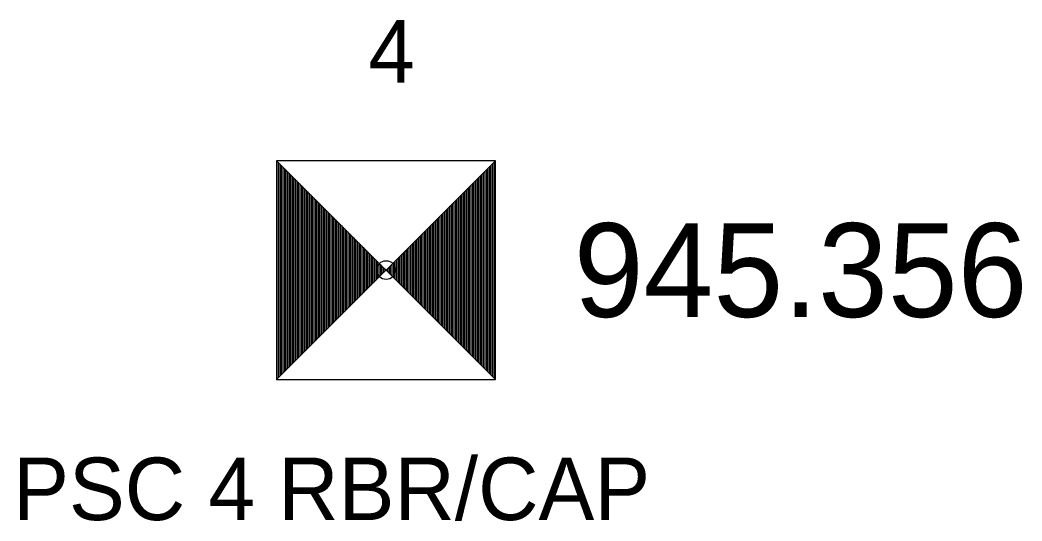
# Model space of a CAD drawing. Extents: x 1448136 to 1453623, y 1125056 to 1128842.
# Drawn here: x 1448135.69 to 1448151.7, y 1126641.44 to 1126649.46 of the extents above; entities that cross this region are included whole.
import ezdxf

# ---------------------------------------------------------------- set-up
doc = ezdxf.new("R2010")
doc.units = 0
for name, color, linetype in [('RD_HC_Survey', 7, 'Continuous'), ('RD_HC_Survey_ELEV', 7, 'Continuous'), ('RD_HC_txCode', 7, 'Continuous'), ('RD_SMD_Locator', 7, 'Continuous')]:
    doc.layers.add(name, color=color, linetype=linetype)

msp = doc.modelspace()

# ---------------------------------------------------------------- linework, layer by layer
at = {"layer": 'RD_HC_Survey'}
for p, q in [((1448139.787, 1126647.205), (1448143.287, 1126643.705)), ((1448143.287, 1126647.205), (1448139.787, 1126643.705)), ((1448139.812, 1126647.18), (1448139.812, 1126643.73)), ((1448143.262, 1126647.18), (1448143.262, 1126643.73)), ((1448139.837, 1126647.156), (1448139.837, 1126643.755)), ((1448139.861, 1126647.131), (1448139.861, 1126643.779)), ((1448139.886, 1126647.106), (1448139.886, 1126643.804)), ((1448139.911, 1126647.081), (1448139.911, 1126643.829)), ((1448139.936, 1126647.057), (1448139.936, 1126643.854)), ((1448139.96, 1126647.032), (1448139.96, 1126643.878)), ((1448139.985, 1126647.007), (1448139.985, 1126643.903)), ((1448143.089, 1126647.007), (1448143.089, 1126643.903)), ((1448143.114, 1126647.032), (1448143.114, 1126643.878)), ((1448143.139, 1126647.057), (1448143.139, 1126643.854)), ((1448143.163, 1126647.081), (1448143.163, 1126643.829)), ((1448143.188, 1126647.106), (1448143.188, 1126643.804)), ((1448143.213, 1126647.131), (1448143.213, 1126643.779)), ((1448143.238, 1126647.156), (1448143.238, 1126643.755)), ((1448140.01, 1126646.982), (1448140.01, 1126643.928)), ((1448140.035, 1126646.958), (1448140.035, 1126643.953)), ((1448140.059, 1126646.933), (1448140.059, 1126643.977)), ((1448140.084, 1126646.908), (1448140.084, 1126644.002)), ((1448140.109, 1126646.883), (1448140.109, 1126644.027)), ((1448140.134, 1126646.859), (1448140.134, 1126644.052)), ((1448142.941, 1126646.859), (1448142.941, 1126644.052)), ((1448142.965, 1126646.883), (1448142.965, 1126644.027)), ((1448142.99, 1126646.908), (1448142.99, 1126644.002)), ((1448143.015, 1126646.933), (1448143.015, 1126643.977)), ((1448143.04, 1126646.958), (1448143.04, 1126643.953)), ((1448143.064, 1126646.982), (1448143.064, 1126643.928)), ((1448140.158, 1126646.834), (1448140.158, 1126644.076)), ((1448140.183, 1126646.809), (1448140.183, 1126644.101)), ((1448140.208, 1126646.784), (1448140.208, 1126644.126)), ((1448140.233, 1126646.76), (1448140.233, 1126644.151)), ((1448140.257, 1126646.735), (1448140.257, 1126644.175)), ((1448140.282, 1126646.71), (1448140.282, 1126644.2)), ((1448140.307, 1126646.685), (1448140.307, 1126644.225)), ((1448142.767, 1126646.685), (1448142.767, 1126644.225)), ((1448142.792, 1126646.71), (1448142.792, 1126644.2)), ((1448142.817, 1126646.735), (1448142.817, 1126644.175)), ((1448142.842, 1126646.76), (1448142.842, 1126644.151)), ((1448142.866, 1126646.784), (1448142.866, 1126644.126)), ((1448142.891, 1126646.809), (1448142.891, 1126644.101)), ((1448142.916, 1126646.834), (1448142.916, 1126644.076)), ((1448140.332, 1126646.661), (1448140.332, 1126644.25)), ((1448140.356, 1126646.636), (1448140.356, 1126644.274)), ((1448140.381, 1126646.611), (1448140.381, 1126644.299)), ((1448140.406, 1126646.586), (1448140.406, 1126644.324)), ((1448140.431, 1126646.562), (1448140.431, 1126644.349)), ((1448140.455, 1126646.537), (1448140.455, 1126644.373)), ((1448142.619, 1126646.537), (1448142.619, 1126644.373)), ((1448142.644, 1126646.562), (1448142.644, 1126644.349)), ((1448142.668, 1126646.586), (1448142.668, 1126644.324)), ((1448142.693, 1126646.611), (1448142.693, 1126644.299)), ((1448142.718, 1126646.636), (1448142.718, 1126644.274)), ((1448142.743, 1126646.661), (1448142.743, 1126644.25)), ((1448140.48, 1126646.512), (1448140.48, 1126644.398)), ((1448140.505, 1126646.487), (1448140.505, 1126644.423)), ((1448140.53, 1126646.463), (1448140.53, 1126644.448)), ((1448140.554, 1126646.438), (1448140.554, 1126644.472)), ((1448140.579, 1126646.413), (1448140.579, 1126644.497)), ((1448140.604, 1126646.388), (1448140.604, 1126644.522)), ((1448140.629, 1126646.364), (1448140.629, 1126644.547)), ((1448142.446, 1126646.364), (1448142.446, 1126644.547)), ((1448142.47, 1126646.388), (1448142.47, 1126644.522)), ((1448142.495, 1126646.413), (1448142.495, 1126644.497)), ((1448142.52, 1126646.438), (1448142.52, 1126644.472)), ((1448142.545, 1126646.463), (1448142.545, 1126644.448)), ((1448142.569, 1126646.487), (1448142.569, 1126644.423)), ((1448142.594, 1126646.512), (1448142.594, 1126644.398)), ((1448140.653, 1126646.339), (1448140.653, 1126644.571)), ((1448140.678, 1126646.314), (1448140.678, 1126644.596)), ((1448140.703, 1126646.289), (1448140.703, 1126644.621)), ((1448140.728, 1126646.265), (1448140.728, 1126644.646)), ((1448140.752, 1126646.24), (1448140.752, 1126644.67)), ((1448140.777, 1126646.215), (1448140.777, 1126644.695)), ((1448142.297, 1126646.215), (1448142.297, 1126644.695)), ((1448142.322, 1126646.24), (1448142.322, 1126644.67)), ((1448142.347, 1126646.265), (1448142.347, 1126644.646)), ((1448142.371, 1126646.289), (1448142.371, 1126644.621)), ((1448142.396, 1126646.314), (1448142.396, 1126644.596)), ((1448142.421, 1126646.339), (1448142.421, 1126644.571)), ((1448140.802, 1126646.19), (1448140.802, 1126644.72)), ((1448140.827, 1126646.166), (1448140.827, 1126644.745)), ((1448140.851, 1126646.141), (1448140.851, 1126644.769)), ((1448140.876, 1126646.116), (1448140.876, 1126644.794)), ((1448140.901, 1126646.091), (1448140.901, 1126644.819)), ((1448140.926, 1126646.067), (1448140.926, 1126644.844)), ((1448140.95, 1126646.042), (1448140.95, 1126644.868)), ((1448142.124, 1126646.042), (1448142.124, 1126644.868)), ((1448142.149, 1126646.067), (1448142.149, 1126644.844)), ((1448142.173, 1126646.091), (1448142.173, 1126644.819)), ((1448142.198, 1126646.116), (1448142.198, 1126644.794)), ((1448142.223, 1126646.141), (1448142.223, 1126644.769)), ((1448142.248, 1126646.166), (1448142.248, 1126644.745)), ((1448142.272, 1126646.19), (1448142.272, 1126644.72)), ((1448140.975, 1126646.017), (1448140.975, 1126644.893)), ((1448141, 1126645.992), (1448141, 1126644.918)), ((1448141.025, 1126645.968), (1448141.025, 1126644.943)), ((1448141.049, 1126645.943), (1448141.049, 1126644.967)), ((1448141.074, 1126645.918), (1448141.074, 1126644.992)), ((1448141.099, 1126645.893), (1448141.099, 1126645.017)), ((1448141.975, 1126645.893), (1448141.975, 1126645.017)), ((1448142, 1126645.918), (1448142, 1126644.992)), ((1448142.025, 1126645.943), (1448142.025, 1126644.967)), ((1448142.05, 1126645.968), (1448142.05, 1126644.943)), ((1448142.074, 1126645.992), (1448142.074, 1126644.918)), ((1448142.099, 1126646.017), (1448142.099, 1126644.893)), ((1448141.124, 1126645.869), (1448141.124, 1126645.042)), ((1448141.148, 1126645.844), (1448141.148, 1126645.066)), ((1448141.173, 1126645.819), (1448141.173, 1126645.091)), ((1448141.198, 1126645.794), (1448141.198, 1126645.116)), ((1448141.223, 1126645.77), (1448141.223, 1126645.141)), ((1448141.247, 1126645.745), (1448141.247, 1126645.165)), ((1448141.827, 1126645.745), (1448141.827, 1126645.165)), ((1448141.852, 1126645.77), (1448141.852, 1126645.141)), ((1448141.876, 1126645.794), (1448141.876, 1126645.116)), ((1448141.901, 1126645.819), (1448141.901, 1126645.091)), ((1448141.926, 1126645.844), (1448141.926, 1126645.066)), ((1448141.951, 1126645.869), (1448141.951, 1126645.042)), ((1448141.272, 1126645.72), (1448141.272, 1126645.19)), ((1448141.297, 1126645.695), (1448141.297, 1126645.215)), ((1448141.322, 1126645.671), (1448141.322, 1126645.24)), ((1448141.346, 1126645.646), (1448141.346, 1126645.264)), ((1448141.371, 1126645.621), (1448141.371, 1126645.289)), ((1448141.396, 1126645.596), (1448141.396, 1126645.314)), ((1448141.421, 1126645.572), (1448141.421, 1126645.339)), ((1448141.654, 1126645.572), (1448141.654, 1126645.339)), ((1448141.678, 1126645.596), (1448141.678, 1126645.314)), ((1448141.703, 1126645.621), (1448141.703, 1126645.289)), ((1448141.728, 1126645.646), (1448141.728, 1126645.264)), ((1448141.753, 1126645.671), (1448141.753, 1126645.24)), ((1448141.777, 1126645.695), (1448141.777, 1126645.215)), ((1448141.802, 1126645.72), (1448141.802, 1126645.19)), ((1448141.445, 1126645.547), (1448141.445, 1126645.363)), ((1448141.47, 1126645.522), (1448141.47, 1126645.388)), ((1448141.495, 1126645.497), (1448141.495, 1126645.413)), ((1448141.52, 1126645.473), (1448141.52, 1126645.438)), ((1448141.555, 1126645.473), (1448141.555, 1126645.438)), ((1448141.579, 1126645.497), (1448141.579, 1126645.413)), ((1448141.604, 1126645.522), (1448141.604, 1126645.388)), ((1448141.629, 1126645.547), (1448141.629, 1126645.363))]:
    msp.add_line(p, q, dxfattribs=at)
msp.add_lwpolyline([(1448143.287, 1126647.205), (1448139.787, 1126647.205), (1448139.787, 1126643.705), (1448143.287, 1126643.705)], close=True, dxfattribs=at)
at = {"layer": 'RD_SMD_Locator'}
msp.add_circle((1448141.537, 1126645.455), 0.15, dxfattribs=at)

# ---------------------------------------------------------------- texts
at = {"layer": 'RD_HC_Survey_ELEV'}
msp.add_text('945.356', height=1.5, dxfattribs=at).set_placement((1448144.537, 1126644.705))
at = {"layer": 'RD_HC_txCode'}
for s, p in [('4', (1448141.254, 1126648.455)), ('PSC 4 RBR/CAP', (1448135.576, 1126641.455))]:
    msp.add_text(s, height=1, dxfattribs=at).set_placement(p)

doc.saveas('drawing.dxf')
